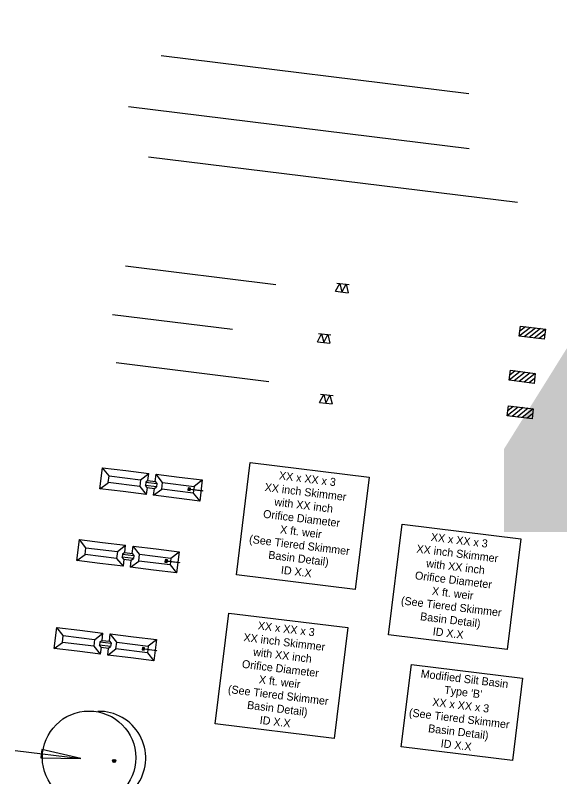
# Model space of a CAD drawing. Extents: x 2470000 to 2520000, y 340000 to 380000.
# Drawn here: x 2482136 to 2482787, y 373379 to 374288 of the extents above; entities that cross this region are included whole.
import ezdxf

# ---------------------------------------------------------------- set-up
doc = ezdxf.new("R2010")
doc.units = 0
for name, color, linetype in [('Modified Silt Basin Type B Note CG CELL', 7, 'Continuous'), ('Riser Basin CG CELL', 7, 'Continuous'), ('Scratch_Level_6', 7, 'Continuous'), ('Sheet Data Field CELL', 7, 'Continuous'), ('Silt Basin Type B Both CELL', 7, 'Continuous'), ('Silt Basin Type B CG CELL', 7, 'Continuous'), ('Silt Basin Type B Final CELL', 7, 'Continuous'), ('Special Sediment Control Fence Both', 7, 'Continuous'), ('Special Sediment Control Fence CG', 7, 'Continuous'), ('Special Sediment Control Fence Final', 7, 'Continuous'), ('Special Sediment Control Fence Section Both CELL', 7, 'Continuous'), ('Special Sediment Control Fence Section CG CELL', 7, 'Continuous'), ('Special Sediment Control Fence Section Final CELL', 7, 'Continuous'), ('Temporary Silt Fence CG', 7, 'Continuous'), ('Temporary Silt Fence Final', 7, 'Continuous'), ('Tiered Skimmer Basin Both CELL', 7, 'Continuous'), ('Tiered Skimmer Basin CG CELL', 7, 'Continuous'), ('Tiered Skimmer Basin Final CELL', 7, 'Continuous'), ('Tiered Skimmer Basin Note Both CELL', 7, 'Continuous'), ('Tiered Skimmer Basin Note CG CELL', 7, 'Continuous'), ('Tiered Skimmer Basin Note Final CELL', 7, 'Continuous')]:
    doc.layers.add(name, color=color, linetype=linetype)

msp = doc.modelspace()

# ---------------------------------------------------------------- linework, layer by layer
at = {"layer": 'Modified Silt Basin Type B Note CG CELL'}
msp.add_lwpolyline([(2482609.52, 373512.61), (2482742.44, 373496.27), (2482730.37, 373398.14), (2482597.46, 373414.48)], close=True, dxfattribs=at)
at = {"layer": 'Riser Basin CG CELL'}
for p, q in [((2482136.17, 373410.03), (2482214.56, 373400.4)), ((2482167.88, 373411.26), (2482166.64, 373401.13)), ((2482214.56, 373400.4), (2482167.88, 373411.26)), ((2482166.64, 373401.13), (2482214.56, 373400.4))]:
    msp.add_line(p, q, dxfattribs=at)
for centre, radius in [((2482224.44, 373401.37), 55.78), ((2482254.38, 373397.45), 1.92), ((2482254.38, 373397.45), 1.91), ((2482254.37, 373397.45), 1.89), ((2482254.37, 373397.45), 1.87), ((2482254.37, 373397.45), 1.85), ((2482254.37, 373397.45), 1.83), ((2482254.37, 373397.45), 1.81), ((2482254.37, 373397.45), 1.8), ((2482254.37, 373397.45), 1.78), ((2482254.37, 373397.45), 1.76), ((2482254.37, 373397.45), 1.74), ((2482254.37, 373397.45), 1.72), ((2482254.37, 373397.45), 1.71), ((2482254.37, 373397.45), 1.69), ((2482254.37, 373397.45), 1.67), ((2482254.36, 373397.45), 1.66), ((2482254.36, 373397.45), 1.64), ((2482254.36, 373397.45), 1.63), ((2482254.24, 373397.47), 0.163), ((2482254.37, 373397.51), 0.163), ((2482254.23, 373397.47), 0.0163), ((2482254.28, 373397.4), 0.00163), ((2482254.37, 373397.52), 0.0163)]:
    msp.add_circle(centre, radius, dxfattribs=at)
msp.add_arc((2482236.39, 373400.97), 55.78, 264.72356, 91.40886, dxfattribs=at)
at = {"layer": 'Sheet Data Field CELL'}
msp.add_line((2482271.61, 374179.19), (2482678.64, 374129.16), dxfattribs=at)
at = {"layer": 'Silt Basin Type B Both CELL'}
for p, q in [((2482739.74, 373862.69), (2482726.36, 373852.19)), ((2482733.72, 373863.33), (2482727.09, 373858.15)), ((2482745.7, 373861.96), (2482732.32, 373851.46)), ((2482751.65, 373861.23), (2482738.28, 373850.78)), ((2482757.61, 373860.49), (2482744.23, 373850)), ((2482756.87, 373854.49), (2482750.19, 373849.31))]:
    msp.add_line(p, q, dxfattribs=at)
msp.add_lwpolyline([(2482727.83, 373864.15), (2482757.61, 373860.49), (2482756.14, 373848.53), (2482726.36, 373852.19)], close=True, dxfattribs=at)
at = {"layer": 'Silt Basin Type B CG CELL'}
for p, q in [((2482751.91, 373915.33), (2482738.53, 373904.84)), ((2482745.9, 373915.97), (2482739.26, 373910.79)), ((2482757.87, 373914.6), (2482744.49, 373904.11)), ((2482763.82, 373913.87), (2482750.45, 373903.42)), ((2482769.78, 373913.14), (2482756.4, 373902.64)), ((2482769.04, 373907.13), (2482762.36, 373901.96))]:
    msp.add_line(p, q, dxfattribs=at)
msp.add_lwpolyline([(2482740, 373916.8), (2482769.78, 373913.14), (2482768.31, 373901.18), (2482738.53, 373904.84)], close=True, dxfattribs=at)
at = {"layer": 'Silt Basin Type B Final CELL'}
for p, q in [((2482737.37, 373820.24), (2482723.99, 373809.74)), ((2482731.36, 373820.88), (2482724.72, 373815.7)), ((2482743.33, 373819.51), (2482729.95, 373809.01)), ((2482749.28, 373818.77), (2482735.91, 373808.33)), ((2482755.24, 373818.04), (2482741.86, 373807.55)), ((2482754.5, 373812.04), (2482747.82, 373806.86))]:
    msp.add_line(p, q, dxfattribs=at)
msp.add_lwpolyline([(2482725.46, 373821.7), (2482755.24, 373818.04), (2482753.77, 373806.08), (2482723.99, 373809.74)], close=True, dxfattribs=at)
at = {"layer": 'Special Sediment Control Fence Both'}
msp.add_line((2482252.47, 373930.79), (2482395.63, 373913.19), dxfattribs=at)
at = {"layer": 'Special Sediment Control Fence CG'}
msp.add_line((2482268.14, 373988.7), (2482447.79, 373966.62), dxfattribs=at)
at = {"layer": 'Special Sediment Control Fence Final'}
msp.add_line((2482256.8, 373873.27), (2482439.26, 373850.84), dxfattribs=at)
at = {"layer": 'Special Sediment Control Fence Section Both CELL'}
for p, q in [((2482498.61, 373908.13), (2482513.5, 373906.3)), ((2482497.39, 373898.2), (2482512.28, 373896.37))]:
    msp.add_line(p, q, dxfattribs=at)
for points in [[(2482497.39, 373898.2), (2482502.34, 373907.67), (2482504.84, 373897.29)], [(2482504.84, 373897.29), (2482509.78, 373906.75), (2482512.28, 373896.37)]]:
    msp.add_lwpolyline(points, dxfattribs=at)
at = {"layer": 'Special Sediment Control Fence Section CG CELL'}
for p, q in [((2482520.31, 373968.37), (2482535.19, 373966.54)), ((2482519.09, 373958.45), (2482533.97, 373956.62))]:
    msp.add_line(p, q, dxfattribs=at)
for points in [[(2482519.09, 373958.45), (2482524.03, 373967.92), (2482526.53, 373957.53)], [(2482526.53, 373957.53), (2482531.47, 373967), (2482533.97, 373956.62)]]:
    msp.add_lwpolyline(points, dxfattribs=at)
at = {"layer": 'Special Sediment Control Fence Section Final CELL'}
for p, q in [((2482501.07, 373835.72), (2482515.96, 373833.89)), ((2482499.85, 373825.8), (2482514.74, 373823.97))]:
    msp.add_line(p, q, dxfattribs=at)
for points in [[(2482499.85, 373825.8), (2482504.8, 373835.27), (2482507.3, 373824.88)], [(2482507.3, 373824.88), (2482512.24, 373834.35), (2482514.74, 373823.97)]]:
    msp.add_lwpolyline(points, dxfattribs=at)
at = {"layer": 'Temporary Silt Fence CG'}
msp.add_line((2482310.42, 374239.96), (2482678.15, 374194.76), dxfattribs=at)
at = {"layer": 'Temporary Silt Fence Final'}
msp.add_line((2482295.58, 374119.26), (2482736.3, 374065.08), dxfattribs=at)
at = {"layer": 'Tiered Skimmer Basin Both CELL'}
for p, q in [((2482209.84, 373636.82), (2482212.95, 373661.98)), ((2482220.68, 373652.25), (2482212.95, 373661.98)), ((2482212.95, 373661.98), (2482240.52, 373658.59)), ((2482219.7, 373644.09), (2482220.68, 373652.25)), ((2482220.68, 373652.25), (2482258.24, 373647.56)), ((2482240.52, 373658.59), (2482268.1, 373655.19)), ((2482258.27, 373647.63), (2482268.1, 373655.19)), ((2482267.04, 373646.5), (2482268.1, 373655.19)), ((2482275.87, 373645.44), (2482276.94, 373654.11)), ((2482284.68, 373644.38), (2482276.94, 373654.11)), ((2482276.94, 373654.11), (2482304.52, 373650.73)), ((2482304.52, 373650.73), (2482332.09, 373647.32)), ((2482209.84, 373636.82), (2482219.71, 373644.05)), ((2482257.24, 373639.44), (2482219.7, 373644.09)), ((2482258.24, 373647.56), (2482257.24, 373639.44)), ((2482264.52, 373644.54), (2482264.09, 373640.87)), ((2482267.04, 373646.5), (2482264.52, 373644.54)), ((2482264.52, 373644.54), (2482277.82, 373642.94)), ((2482267.04, 373646.5), (2482275.87, 373645.44)), ((2482275.87, 373645.44), (2482277.82, 373642.94)), ((2482277.82, 373642.94), (2482277.37, 373639.26)), ((2482283.69, 373636.22), (2482284.68, 373644.38)), ((2482284.68, 373644.38), (2482322.24, 373639.7)), ((2482322.26, 373639.76), (2482332.09, 373647.32)), ((2482332.09, 373647.32), (2482329.02, 373622.17)), ((2482237.46, 373633.42), (2482209.84, 373636.82)), ((2482265.05, 373630.01), (2482237.46, 373633.42)), ((2482257.24, 373639.44), (2482265.02, 373630.03)), ((2482266.04, 373638.37), (2482264.09, 373640.87)), ((2482277.37, 373639.26), (2482264.09, 373640.87)), ((2482266.04, 373638.37), (2482265.02, 373630.03)), ((2482266.04, 373638.37), (2482274.86, 373637.29)), ((2482273.83, 373628.95), (2482274.86, 373637.29)), ((2482273.83, 373628.95), (2482283.7, 373636.19)), ((2482274.86, 373637.29), (2482277.37, 373639.26)), ((2482321.24, 373631.57), (2482283.69, 373636.22)), ((2482315.31, 373637.88), (2482314.96, 373635.03)), ((2482314.96, 373635.03), (2482317.6, 373634.7)), ((2482317.95, 373637.55), (2482315.31, 373637.88)), ((2482315.72, 373637.35), (2482315.48, 373635.44)), ((2482315.48, 373635.44), (2482317.19, 373635.23)), ((2482317.43, 373637.14), (2482315.72, 373637.35)), ((2482317.19, 373635.23), (2482317.43, 373637.14)), ((2482317.6, 373634.7), (2482317.95, 373637.55)), ((2482332.33, 373634.09), (2482317.75, 373635.89)), ((2482317.8, 373636.36), (2482332.38, 373634.54)), ((2482322.24, 373639.7), (2482321.24, 373631.57)), ((2482332.38, 373634.54), (2482332.33, 373634.09)), ((2482301.46, 373625.55), (2482273.83, 373628.95)), ((2482329.05, 373622.15), (2482301.46, 373625.55)), ((2482321.24, 373631.57), (2482329.02, 373622.17))]:
    msp.add_line(p, q, dxfattribs=at)
at = {"layer": 'Tiered Skimmer Basin CG CELL'}
for p, q in [((2482237.47, 373722.64), (2482240.58, 373747.8)), ((2482248.32, 373738.06), (2482240.58, 373747.8)), ((2482240.58, 373747.8), (2482268.16, 373744.41)), ((2482268.16, 373744.41), (2482295.74, 373741)), ((2482247.33, 373729.91), (2482248.32, 373738.06)), ((2482248.32, 373738.06), (2482285.88, 373733.38)), ((2482285.88, 373733.38), (2482284.88, 373725.26)), ((2482285.9, 373733.44), (2482295.74, 373741)), ((2482294.67, 373732.32), (2482292.16, 373730.36)), ((2482294.67, 373732.32), (2482295.74, 373741)), ((2482294.67, 373732.32), (2482303.51, 373731.26)), ((2482303.51, 373731.26), (2482304.58, 373739.93)), ((2482312.32, 373730.2), (2482304.58, 373739.93)), ((2482304.58, 373739.93), (2482332.16, 373736.54)), ((2482332.16, 373736.54), (2482359.73, 373733.14)), ((2482349.9, 373725.58), (2482359.73, 373733.14)), ((2482359.73, 373733.14), (2482356.66, 373707.99)), ((2482237.47, 373722.64), (2482247.35, 373729.87)), ((2482284.88, 373725.26), (2482247.33, 373729.91)), ((2482284.88, 373725.26), (2482292.66, 373715.85)), ((2482292.16, 373730.36), (2482291.72, 373726.69)), ((2482293.68, 373724.19), (2482291.72, 373726.69)), ((2482305.01, 373725.07), (2482291.72, 373726.69)), ((2482292.16, 373730.36), (2482305.46, 373728.76)), ((2482293.68, 373724.19), (2482292.66, 373715.85)), ((2482293.68, 373724.19), (2482302.5, 373723.11)), ((2482302.5, 373723.11), (2482305.01, 373725.07)), ((2482303.51, 373731.26), (2482305.46, 373728.76)), ((2482305.46, 373728.76), (2482305.01, 373725.07)), ((2482311.33, 373722.04), (2482312.32, 373730.2)), ((2482312.32, 373730.2), (2482349.88, 373725.51)), ((2482342.95, 373723.7), (2482342.6, 373720.85)), ((2482345.59, 373723.37), (2482342.95, 373723.7)), ((2482345.24, 373720.52), (2482345.59, 373723.37)), ((2482349.88, 373725.51), (2482348.88, 373717.39)), ((2482265.1, 373719.24), (2482237.47, 373722.64)), ((2482292.69, 373715.83), (2482265.1, 373719.24)), ((2482301.47, 373714.77), (2482302.5, 373723.11)), ((2482301.47, 373714.77), (2482311.34, 373722)), ((2482329.09, 373711.37), (2482301.47, 373714.77)), ((2482348.88, 373717.39), (2482311.33, 373722.04)), ((2482342.6, 373720.85), (2482345.24, 373720.52)), ((2482343.36, 373723.17), (2482343.12, 373721.26)), ((2482343.12, 373721.26), (2482344.83, 373721.05)), ((2482345.07, 373722.96), (2482343.36, 373723.17)), ((2482344.83, 373721.05), (2482345.07, 373722.96)), ((2482359.97, 373719.91), (2482345.39, 373721.71)), ((2482345.44, 373722.18), (2482360.02, 373720.36)), ((2482348.88, 373717.39), (2482356.66, 373707.99)), ((2482360.02, 373720.36), (2482359.96, 373719.91)), ((2482356.69, 373707.96), (2482329.09, 373711.37))]:
    msp.add_line(p, q, dxfattribs=at)
at = {"layer": 'Tiered Skimmer Basin Final CELL'}
for p, q in [((2482182.69, 373531.87), (2482185.8, 373557.04)), ((2482193.54, 373547.3), (2482185.8, 373557.04)), ((2482185.8, 373557.04), (2482213.37, 373553.65)), ((2482213.37, 373553.65), (2482240.95, 373550.24)), ((2482192.55, 373539.14), (2482193.54, 373547.3)), ((2482193.54, 373547.3), (2482231.09, 373542.62)), ((2482231.09, 373542.62), (2482230.1, 373534.49)), ((2482231.12, 373542.68), (2482240.95, 373550.24)), ((2482239.89, 373541.56), (2482237.37, 373539.6)), ((2482239.89, 373541.56), (2482240.95, 373550.24)), ((2482239.89, 373541.56), (2482248.72, 373540.5)), ((2482248.72, 373540.5), (2482249.79, 373549.17)), ((2482257.53, 373539.44), (2482249.79, 373549.17)), ((2482249.79, 373549.17), (2482277.37, 373545.78)), ((2482277.37, 373545.78), (2482304.94, 373542.37)), ((2482295.11, 373534.82), (2482304.94, 373542.37)), ((2482304.94, 373542.37), (2482301.87, 373517.22)), ((2482182.69, 373531.87), (2482192.56, 373539.11)), ((2482230.1, 373534.49), (2482192.55, 373539.14)), ((2482230.1, 373534.49), (2482237.87, 373525.09)), ((2482237.37, 373539.6), (2482236.94, 373535.93)), ((2482238.89, 373533.42), (2482236.94, 373535.93)), ((2482250.22, 373534.31), (2482236.94, 373535.93)), ((2482237.37, 373539.6), (2482250.67, 373537.99)), ((2482238.89, 373533.42), (2482237.87, 373525.09)), ((2482238.89, 373533.42), (2482247.71, 373532.35)), ((2482246.68, 373524.01), (2482247.71, 373532.35)), ((2482247.71, 373532.35), (2482250.22, 373534.31)), ((2482248.72, 373540.5), (2482250.67, 373537.99)), ((2482250.67, 373537.99), (2482250.22, 373534.31)), ((2482256.54, 373531.28), (2482257.53, 373539.44)), ((2482257.53, 373539.44), (2482295.09, 373534.75)), ((2482288.16, 373532.93), (2482287.81, 373530.09)), ((2482290.8, 373532.6), (2482288.16, 373532.93)), ((2482288.57, 373532.41), (2482288.33, 373530.5)), ((2482290.28, 373532.2), (2482288.57, 373532.41)), ((2482290.04, 373530.28), (2482290.28, 373532.2)), ((2482290.45, 373529.76), (2482290.8, 373532.6)), ((2482295.09, 373534.75), (2482294.09, 373526.63)), ((2482210.31, 373528.48), (2482182.69, 373531.87)), ((2482237.91, 373525.07), (2482210.31, 373528.48)), ((2482246.68, 373524.01), (2482256.56, 373531.24)), ((2482274.31, 373520.61), (2482246.68, 373524.01)), ((2482294.09, 373526.63), (2482256.54, 373531.28)), ((2482287.81, 373530.09), (2482290.45, 373529.76)), ((2482288.33, 373530.5), (2482290.04, 373530.28)), ((2482305.18, 373529.14), (2482290.6, 373530.95)), ((2482290.66, 373531.41), (2482305.23, 373529.6)), ((2482294.09, 373526.63), (2482301.87, 373517.22)), ((2482305.24, 373529.6), (2482305.18, 373529.14)), ((2482301.9, 373517.2), (2482274.31, 373520.61))]:
    msp.add_line(p, q, dxfattribs=at)
at = {"layer": 'Tiered Skimmer Basin Note Both CELL'}
msp.add_lwpolyline([(2482391.55, 373574.18), (2482533.56, 373556.72), (2482517.29, 373424.33), (2482375.27, 373441.79)], close=True, dxfattribs=at)
at = {"layer": 'Tiered Skimmer Basin Note CG CELL'}
msp.add_lwpolyline([(2482416.92, 373753.86), (2482558.94, 373736.41), (2482542.45, 373602.3), (2482400.43, 373619.75)], close=True, dxfattribs=at)
at = {"layer": 'Tiered Skimmer Basin Note Final CELL'}
msp.add_lwpolyline([(2482598.37, 373680.41), (2482740.39, 373662.96), (2482724.12, 373530.57), (2482582.1, 373548.03)], close=True, dxfattribs=at)

# ---------------------------------------------------------------- texts
at = {"layer": 'Modified Silt Basin Type B Note CG CELL'}
for s, height, p in [('Modified Silt Basin', 9.5659, (2482620.31, 373497.31)), ("Type 'B'", 9.566, (2482648.39, 373477.8)), ('XX x XX x 3', 9.5659, (2482634.19, 373463.48)), ('(See Tiered Skimmer', 9.5659, (2482606.27, 373450.85)), ('Basin Detail)', 9.5659, (2482629.2, 373431.97)), ('ID X.X', 9.566, (2482644.23, 373414.06))]:
    msp.add_text(s, height=height, rotation=352.99213, dxfattribs=at).set_placement(p)
at = {"layer": 'Scratch_Level_6'}
msp.add_text('4387', height=1000, dxfattribs=at).set_placement((2482689.75, 373444.66))
at = {"layer": 'Tiered Skimmer Basin Note Both CELL'}
for s, height, p in [('XX x XX x 3', 9.5659, (2482425.66, 373554.7)), ('XX inch Skimmer', 9.5659, (2482408.55, 373540.74)), ('with XX inch', 9.5659, (2482420.14, 373523.25)), ('Orifice Diameter', 9.5659, (2482406.68, 373508.84)), ('X ft. weir', 9.566, (2482426.96, 373490.29)), ('(See Tiered Skimmer', 9.5659, (2482389.96, 373478.77)), ('Basin Detail)', 9.5659, (2482412.89, 373459.89)), ('ID X.X', 9.566, (2482427.92, 373441.98))]:
    msp.add_text(s, height=height, rotation=352.99213, dxfattribs=at).set_placement(p)
at = {"layer": 'Tiered Skimmer Basin Note CG CELL'}
for s, height, p in [('XX x XX x 3', 9.5659, (2482450.98, 373733.96)), ('XX inch Skimmer', 9.5659, (2482433.86, 373720)), ('with XX inch', 9.5659, (2482445.45, 373702.51)), ('Orifice Diameter', 9.5659, (2482432, 373688.1)), ('X ft. weir', 9.566, (2482452.28, 373669.54)), ('(See Tiered Skimmer', 9.5659, (2482415.28, 373658.03)), ('Basin Detail)', 9.5659, (2482438.21, 373639.15)), ('ID X.X', 9.566, (2482453.24, 373621.24))]:
    msp.add_text(s, height=height, rotation=352.99213, dxfattribs=at).set_placement(p)
at = {"layer": 'Tiered Skimmer Basin Note Final CELL'}
for s, height, p in [('XX x XX x 3', 9.5659, (2482632.43, 373660.51)), ('XX inch Skimmer', 9.5659, (2482615.32, 373646.55)), ('with XX inch', 9.5659, (2482626.91, 373629.06)), ('Orifice Diameter', 9.5659, (2482613.45, 373614.65)), ('X ft. weir', 9.566, (2482633.73, 373596.09)), ('(See Tiered Skimmer', 9.5659, (2482596.73, 373584.58)), ('Basin Detail)', 9.5659, (2482619.66, 373565.7)), ('ID X.X', 9.566, (2482634.69, 373547.79))]:
    msp.add_text(s, height=height, rotation=352.99213, dxfattribs=at).set_placement(p)

doc.saveas('drawing.dxf')
